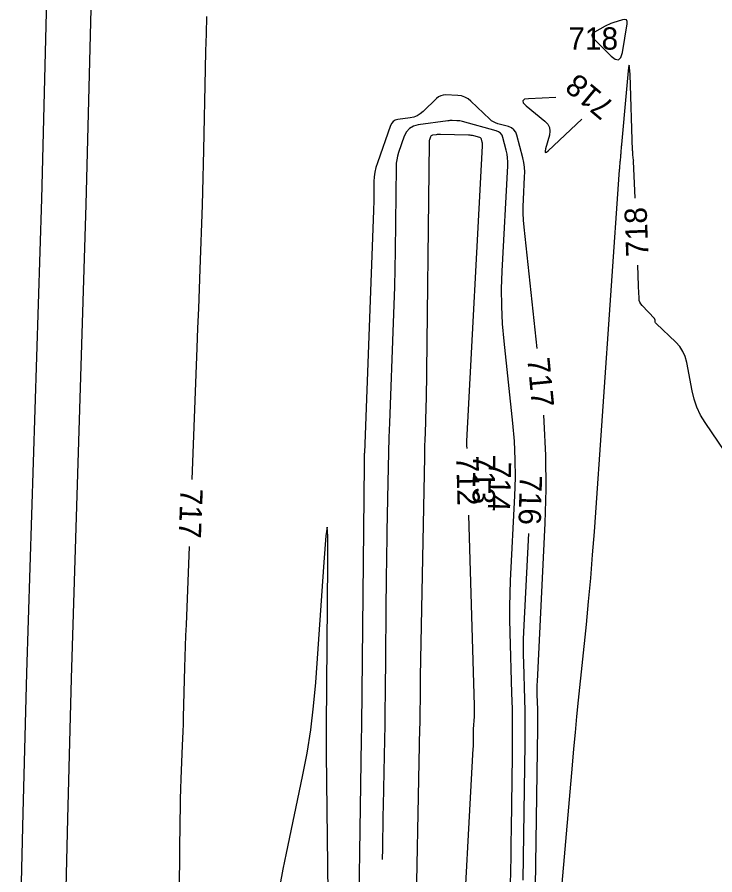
# Model space of a CAD drawing. Extents: x -361782338 to 28259792, y -263199453 to 8342113.
# Drawn here: x 1403799.4 to 1403924.5, y 577082 to 577235.8 of the extents above; entities that cross this region are included whole.
import ezdxf

# ---------------------------------------------------------------- set-up
doc = ezdxf.new("R2010")
doc.units = 0
for name, color, linetype in [('DT_X_Contour_Minor', 7, 'Continuous'), ('Level 19', 7, 'Continuous'), ('Level 56', 7, 'Continuous')]:
    doc.layers.add(name, color=color, linetype=linetype)

msp = doc.modelspace()

# ---------------------------------------------------------------- linework, layer by layer
at = {"layer": 'DT_X_Contour_Minor'}
for points in [[(1403830.74, 577152.87), (1403831.66, 577176.51), (1403831.8, 577180.02), (1403831.93, 577183.54), (1403832.06, 577187.06), (1403832.18, 577190.58), (1403832.59, 577202.07), (1403832.67, 577204.53), (1403832.75, 577206.99), (1403832.81, 577209.45), (1403832.86, 577211.92), (1403833.16, 577226.52), (1403833.23, 577229.65), (1403833.31, 577232.77), (1403833.4, 577235.9)], [(1403902.74, 577231.95), (1403905.91, 577228.79), (1403906.65, 577228.22), (1403907.24, 577228.14), (1403907.66, 577228.55), (1403907.93, 577229.45), (1403908.77, 577234.57), (1403908.79, 577235.02), (1403908.65, 577235.29), (1403908.36, 577235.38), (1403907.92, 577235.3), (1403906.22, 577234.74), (1403905.86, 577234.62), (1403905.51, 577234.47), (1403905.17, 577234.31), (1403904.83, 577234.14), (1403902.9, 577233.07), (1403902.58, 577232.83), (1403902.45, 577232.57), (1403902.5, 577232.27), (1403902.74, 577231.95)], [(1403910.2, 577203.3), (1403909.93, 577209.95), (1403909.93, 577209.96), (1403909.93, 577209.96), (1403909.93, 577209.96), (1403909.94, 577209.96), (1403909.94, 577209.95), (1403909.95, 577209.95), (1403909.95, 577209.95), (1403909.95, 577209.95), (1403909.95, 577209.95), (1403909.94, 577210.09), (1403909.94, 577210.1), (1403909.94, 577210.1), (1403909.94, 577210.1), (1403909.94, 577210.1), (1403909.94, 577210.09), (1403909.94, 577210.09), (1403909.94, 577210.09), (1403909.94, 577210.09), (1403909.94, 577210.09), (1403909.94, 577210.11), (1403909.94, 577210.11), (1403909.94, 577210.12), (1403909.94, 577210.12), (1403909.94, 577210.13), (1403909.82, 577211.07), (1403909.8, 577211.28), (1403909.78, 577211.48), (1403909.77, 577211.68), (1403909.76, 577211.89), (1403909.29, 577225.49), (1403909.22, 577226.77), (1403909.13, 577227.19), (1403909.02, 577226.77), (1403908.88, 577225.5), (1403908.18, 577217.6), (1403908.18, 577217.6), (1403908.18, 577217.6), (1403908.18, 577217.59), (1403908.18, 577217.59), (1403908.18, 577217.59), (1403908.18, 577217.59), (1403908.18, 577217.59), (1403908.18, 577217.59), (1403908.18, 577217.59), (1403908.17, 577217.55), (1403908.17, 577217.55), (1403908.17, 577217.54), (1403908.17, 577217.53), (1403908.17, 577217.52), (1403907.76, 577212.94), (1403907.76, 577212.89), (1403907.76, 577212.84), (1403907.75, 577212.8), (1403907.75, 577212.75), (1403907.73, 577212.56), (1403907.73, 577212.55), (1403907.73, 577212.53), (1403907.73, 577212.52), (1403907.73, 577212.51), (1403907.72, 577212.47), (1403907.72, 577212.46), (1403907.72, 577212.45), (1403907.72, 577212.44), (1403907.72, 577212.44), (1403907.65, 577211.61), (1403907.63, 577211.43), (1403907.62, 577211.26), (1403907.6, 577211.08), (1403907.58, 577210.9), (1403907.5, 577209.97), (1403907.5, 577209.93), (1403907.49, 577209.89), (1403907.49, 577209.84), (1403907.49, 577209.8), (1403907.47, 577209.66), (1403907.47, 577209.64), (1403907.47, 577209.61), (1403907.47, 577209.58), (1403907.46, 577209.55), (1403907.42, 577209.04), (1403907.42, 577209.02), (1403907.42, 577209), (1403907.41, 577208.97), (1403907.41, 577208.95), (1403907.4, 577208.87), (1403907.4, 577208.85), (1403907.4, 577208.83), (1403907.4, 577208.82), (1403907.4, 577208.8), (1403907.38, 577208.58), (1403907.38, 577208.54), (1403907.37, 577208.49), (1403907.37, 577208.44), (1403907.36, 577208.4), (1403902.83, 577143.51), (1403902.52, 577139.35), (1403902.18, 577135.19), (1403901.81, 577131.03), (1403901.4, 577126.88)], [(1403892.63, 577176.37), (1403890.31, 577198.14), (1403890.2, 577199.37), (1403890.15, 577200.61), (1403890.14, 577201.85), (1403890.18, 577203.09), (1403890.39, 577207.14), (1403890.41, 577208), (1403890.35, 577208.86), (1403890.24, 577209.71), (1403890.05, 577210.56), (1403889.01, 577214.62), (1403888.8, 577215.16), (1403888.48, 577215.59), (1403888.05, 577215.92), (1403887.52, 577216.14), (1403885.59, 577216.67), (1403885.19, 577216.8), (1403884.81, 577216.99), (1403884.46, 577217.21), (1403884.14, 577217.49), (1403880.76, 577220.73), (1403880.25, 577221.14), (1403879.69, 577221.45), (1403879.08, 577221.64), (1403878.43, 577221.73), (1403876.22, 577221.83), (1403875.76, 577221.8), (1403875.34, 577221.69), (1403874.95, 577221.49), (1403874.59, 577221.21), (1403872.19, 577218.87), (1403871.68, 577218.44), (1403871.12, 577218.1), (1403870.51, 577217.86), (1403869.85, 577217.72), (1403867.62, 577217.41), (1403867.19, 577217.3), (1403866.83, 577217.09), (1403866.55, 577216.78), (1403866.35, 577216.37), (1403863.97, 577209.64), (1403863.72, 577208.82), (1403863.53, 577207.99), (1403863.42, 577207.15), (1403863.37, 577206.3), (1403863.34, 577203.49), (1403863.33, 577202.89), (1403863.32, 577202.29), (1403863.3, 577201.69), (1403863.28, 577201.09), (1403861.64, 577157.67), (1403861.63, 577157.46), (1403861.63, 577157.25), (1403861.62, 577157.05), (1403861.62, 577156.84), (1403861.6, 577156.16), (1403861.6, 577156.01), (1403861.6, 577155.87), (1403861.6, 577155.72), (1403861.6, 577155.58), (1403861.12, 577108.88), (1403861.11, 577108.61), (1403861.11, 577108.35), (1403861.11, 577108.09), (1403861.1, 577107.83), (1403861.08, 577106.97), (1403861.08, 577106.78), (1403861.08, 577106.6), (1403861.07, 577106.42), (1403861.07, 577106.23), (1403860.42, 577061.79)], [(1403896.01, 577221.39), (1403891.08, 577221.15), (1403890.35, 577221.04), (1403890.04, 577220.79), (1403890.14, 577220.4), (1403890.65, 577219.87)], [(1403890.65, 577219.87), (1403894.03, 577217.1), (1403894.53, 577216.57), (1403894.83, 577215.98), (1403894.93, 577215.32), (1403894.82, 577214.6), (1403894.13, 577212.14), (1403894.05, 577211.72), (1403894.1, 577211.53), (1403894.3, 577211.57), (1403894.63, 577211.83), (1403900.63, 577217.51)], [(1403878.22, 577217.21), (1403877.37, 577217.23), (1403877.18, 577217.23), (1403877, 577217.23), (1403876.82, 577217.21), (1403876.63, 577217.19), (1403871.32, 577216.46), (1403870.46, 577216.23), (1403869.76, 577215.82), (1403869.21, 577215.21), (1403868.81, 577214.41), (1403867.78, 577211.49), (1403867.58, 577210.86), (1403867.44, 577210.22), (1403867.36, 577209.57), (1403867.32, 577208.91), (1403867.14, 577193.87), (1403867.09, 577190.65), (1403867.03, 577187.42), (1403866.93, 577184.2), (1403866.82, 577180.98), (1403866.15, 577163.06), (1403866.05, 577160.38), (1403865.97, 577157.7), (1403865.9, 577155.02), (1403865.84, 577152.33), (1403865.69, 577143.57), (1403865.65, 577141.69), (1403865.62, 577139.81), (1403865.6, 577137.93), (1403865.58, 577136.05), (1403865.36, 577114.36), (1403865.33, 577111.62), (1403865.29, 577108.87), (1403865.24, 577106.13), (1403865.19, 577103.38), (1403865, 577094.42), (1403864.96, 577092.49), (1403864.93, 577090.57), (1403864.9, 577088.65), (1403864.87, 577086.73), (1403864.84, 577084.75)], [(1403887.86, 577080.22), (1403887.91, 577082.73), (1403887.95, 577085.24), (1403887.99, 577087.74), (1403888.02, 577090.25), (1403888.21, 577103.35), (1403888.23, 577106.16), (1403888.23, 577108.96), (1403888.19, 577111.77), (1403888.12, 577114.57), (1403887.79, 577125.44), (1403887.75, 577127.77), (1403887.74, 577130.09), (1403887.79, 577132.42), (1403887.88, 577134.75), (1403888.64, 577149.97), (1403888.73, 577153.23), (1403888.7, 577156.48), (1403888.55, 577159.73), (1403888.27, 577162.98), (1403886.7, 577177.65), (1403886.43, 577180.79), (1403886.28, 577183.94), (1403886.26, 577187.09), (1403886.36, 577190.24), (1403887.36, 577209.12), (1403887.37, 577209.83), (1403887.33, 577210.53), (1403887.23, 577211.23), (1403887.08, 577211.92), (1403886.5, 577214.17), (1403886.33, 577214.61), (1403886.08, 577214.96), (1403885.73, 577215.22), (1403885.29, 577215.4), (1403879.26, 577217.06), (1403879, 577217.12), (1403878.75, 577217.17), (1403878.49, 577217.2), (1403878.22, 577217.21)], [(1403880.06, 577158.45), (1403880.06, 577158.49), (1403880.04, 577158.91), (1403880.04, 577159.34), (1403880.05, 577159.76), (1403882.84, 577212.71), (1403882.85, 577212.88), (1403882.84, 577213.04), (1403882.81, 577213.2), (1403882.78, 577213.37), (1403882.64, 577213.89), (1403882.6, 577214), (1403882.54, 577214.08), (1403882.46, 577214.14), (1403882.36, 577214.18), (1403881.29, 577214.48), (1403881.06, 577214.53), (1403880.82, 577214.58), (1403880.59, 577214.6), (1403880.35, 577214.62), (1403875.28, 577214.74), (1403875.08, 577214.74), (1403874.89, 577214.74), (1403874.7, 577214.72), (1403874.5, 577214.7), (1403873.88, 577214.61), (1403873.75, 577214.58), (1403873.65, 577214.52), (1403873.57, 577214.43), (1403873.52, 577214.32), (1403873.33, 577213.79), (1403873.29, 577213.67), (1403873.27, 577213.56), (1403873.25, 577213.44), (1403873.25, 577213.32), (1403872.7, 577167.15), (1403872.69, 577166.14), (1403872.66, 577165.13), (1403872.63, 577164.11), (1403872.6, 577163.1), (1403872.47, 577159.79), (1403872.45, 577159.08), (1403872.43, 577158.37), (1403872.41, 577157.66), (1403872.4, 577156.95), (1403871.68, 577117.55), (1403871.66, 577116.64), (1403871.65, 577115.72), (1403871.64, 577114.81), (1403871.63, 577113.9), (1403871.6, 577110.93), (1403871.59, 577110.29), (1403871.58, 577109.66), (1403871.57, 577109.02), (1403871.56, 577108.38), (1403870.73, 577068.44)], [(1403917.5, 577177.5), (1403913.98, 577180.84), (1403913.92, 577180.91), (1403913.87, 577180.99), (1403913.83, 577181.08), (1403913.81, 577181.18), (1403913.78, 577181.51), (1403913.77, 577181.57), (1403913.75, 577181.64), (1403913.71, 577181.7), (1403913.67, 577181.75), (1403911.44, 577184.08), (1403911.22, 577184.36), (1403911.06, 577184.67), (1403910.95, 577184.99), (1403910.91, 577185.35), (1403910.86, 577186.55), (1403910.85, 577186.81), (1403910.84, 577187.06), (1403910.83, 577187.32), (1403910.82, 577187.58), (1403910.67, 577191.31)], [(1403930.96, 577151.01), (1403922.77, 577163.09), (1403921.96, 577164.42), (1403921.3, 577165.82), (1403920.79, 577167.27), (1403920.43, 577168.79), (1403919.47, 577173.88), (1403919.2, 577174.91), (1403918.78, 577175.85), (1403918.21, 577176.72), (1403917.5, 577177.5)], [(1403892.24, 577071.78), (1403892.75, 577108.3), (1403892.76, 577109.13), (1403892.76, 577109.95), (1403892.75, 577110.78), (1403892.73, 577111.61), (1403892.65, 577114.31), (1403892.63, 577114.89), (1403892.63, 577115.47), (1403892.65, 577116.05), (1403892.67, 577116.63), (1403894.07, 577145.04), (1403894.26, 577151.12), (1403894.2, 577157.2), (1403893.91, 577163.27), (1403893.81, 577164.42)], [(1403881.41, 577112.35), (1403880.38, 577146.47)], [(1403855.33, 577063.69), (1403854.88, 577103.71), (1403854.88, 577104.2), (1403854.87, 577104.69), (1403854.86, 577105.17), (1403854.86, 577105.66), (1403854.84, 577107.25), (1403854.84, 577107.59), (1403854.84, 577107.93), (1403854.84, 577108.28), (1403854.84, 577108.62), (1403855.1, 577138.01), (1403855.1, 577142.74), (1403854.97, 577144.32), (1403854.72, 577142.75), (1403854.35, 577138.04), (1403852.86, 577116.49), (1403852.49, 577112.23), (1403851.98, 577108), (1403851.32, 577103.79), (1403850.51, 577099.6), (1403847.62, 577085.89), (1403847.03, 577082.98), (1403846.48, 577080.07)], [(1403890.13, 577081.02), (1403890.48, 577105.46), (1403890.49, 577107.46), (1403890.49, 577109.46), (1403890.46, 577111.46), (1403890.41, 577113.46), (1403890.22, 577119.99), (1403890.19, 577121.39), (1403890.19, 577122.78), (1403890.21, 577124.18), (1403890.27, 577125.58), (1403891.14, 577143.18)], [(1403827.98, 577031.29), (1403828.62, 577091.93), (1403828.65, 577093.75), (1403828.68, 577095.57), (1403828.74, 577097.39), (1403828.8, 577099.22), (1403829.04, 577105.16), (1403829.09, 577106.44), (1403829.14, 577107.71), (1403829.18, 577108.99), (1403829.21, 577110.26), (1403829.47, 577119.17), (1403829.52, 577121.08), (1403829.59, 577122.99), (1403829.65, 577124.89), (1403829.72, 577126.8), (1403830.27, 577140.88)], [(1403901.4, 577126.88), (1403900, 577113.31), (1403899.71, 577110.4), (1403899.43, 577107.49), (1403899.16, 577104.58), (1403898.9, 577101.67), (1403896.42, 577072.89)], [(1403879.04, 577065.89), (1403881.17, 577104.62), (1403881.19, 577104.96), (1403881.2, 577105.31), (1403881.21, 577105.66), (1403881.21, 577106), (1403881.21, 577107.13), (1403881.21, 577107.37), (1403881.22, 577107.62), (1403881.23, 577107.86), (1403881.24, 577108.1), (1403881.38, 577110.39), (1403881.4, 577110.88), (1403881.41, 577111.37), (1403881.42, 577111.86), (1403881.41, 577112.35)]]:
    msp.add_lwpolyline(points, dxfattribs=at)
at = {"layer": 'Level 56'}
for points in [[(1403799.72, 576951.13), (1403799.37, 577003.24), (1403799.52, 577053.24), (1403800.45, 577093.03), (1403801.13, 577118.22), (1403803.77, 577203.2), (1403806.32, 577303.59), (1403809.79, 577453.55), (1403811.89, 577528.32), (1403813.35, 577578.3), (1403815.32, 577653.47), (1403817.33, 577718.44), (1403820.35, 577828.2), (1403822.42, 577903.37), (1403824.98, 578003.34), (1403826.21, 578053.33), (1403828.88, 578143.09), (1403833.01, 578278.03), (1403835.33, 578353.19), (1403836.58, 578403.18), (1403837.59, 578489.24)], [(1403807.71, 576950.11), (1403807.36, 577002.22), (1403807.51, 577052.22), (1403808.43, 577092.01), (1403809.12, 577117.2), (1403811.75, 577202.18), (1403814.31, 577302.57), (1403817.77, 577452.53), (1403819.88, 577527.3), (1403821.33, 577577.28), (1403823.31, 577652.45), (1403825.32, 577717.42), (1403828.34, 577827.18), (1403830.4, 577902.36), (1403832.96, 578002.32), (1403834.2, 578052.31), (1403836.87, 578142.07), (1403841, 578277.01), (1403843.32, 578352.18), (1403844.57, 578402.16), (1403845.58, 578488.22)]]:
    msp.add_lwpolyline(points, dxfattribs=at)

# ---------------------------------------------------------------- texts
at = {"layer": 'Level 19'}
msp.add_text('718', height=4, dxfattribs=at).set_placement((1403898.23, 577229.95))
for s, rotation, p in [('718', 140.009, (1403906.75, 577220.18)), ('718', 92.2751, (1403912.61, 577192.86)), ('717', 275.6319, (1403890.85, 577174.56)), ('712', 271.5177, (1403878.12, 577157.06)), ('713', 269.4178, (1403881.14, 577157.41)), ('714', 268.5859, (1403883.99, 577156.13)), ('716', 268.4409, (1403889.53, 577153.7)), ('717', 267.7668, (1403828.68, 577151.33))]:
    msp.add_text(s, height=4, rotation=rotation, dxfattribs=at).set_placement(p)

doc.saveas('drawing.dxf')
